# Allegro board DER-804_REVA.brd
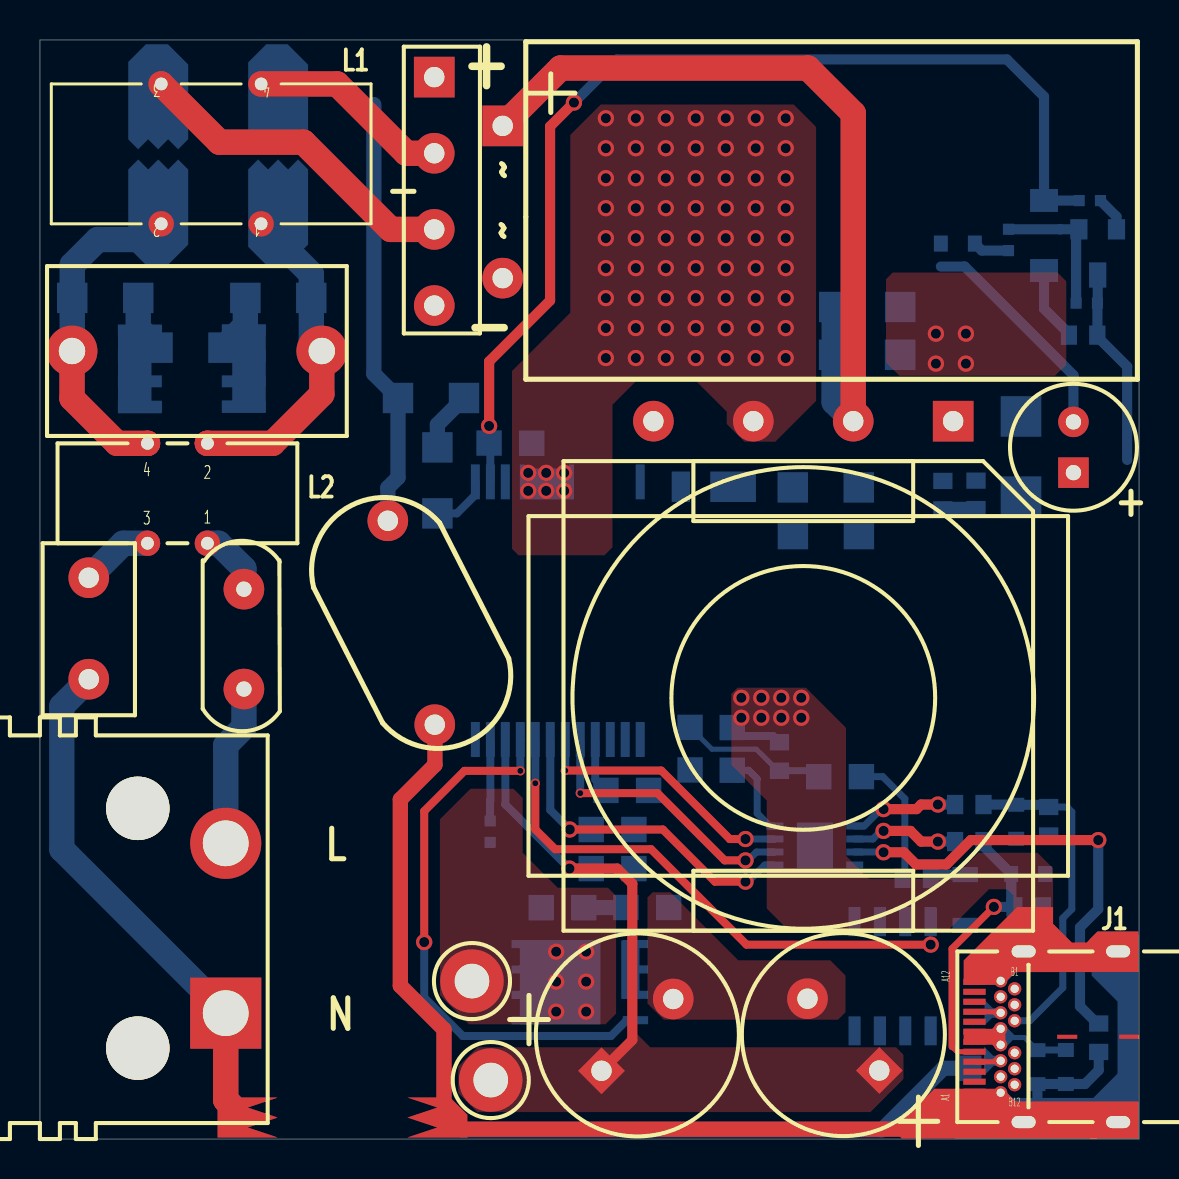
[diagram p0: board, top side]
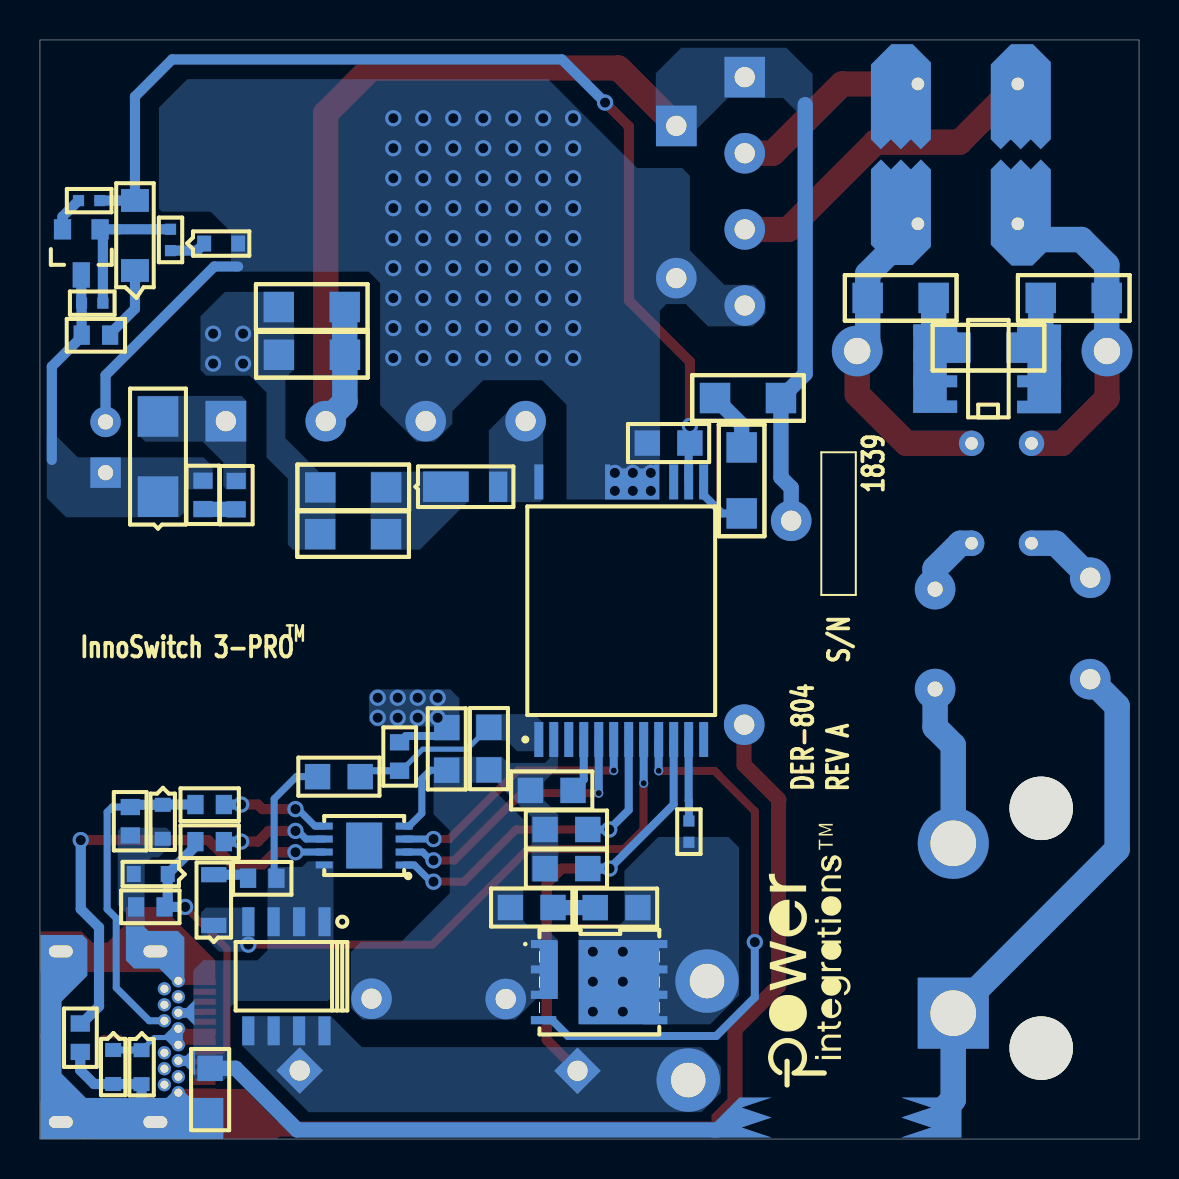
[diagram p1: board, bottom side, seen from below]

Outline 55 x 55 mm; copper layers: TOP, BOTTOM. Coordinates in mm from the lower left corner of the outline.
Outline path: 0,55 55,55 55,0 0,0 0,55

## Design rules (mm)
constraint set DEFAULT: min track width 0.508

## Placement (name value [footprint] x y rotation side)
BR1  UD4KB100-BP  [PIDAXBRIDGED3K]  19.73 53.14 270 top
C1  1 nF  [PINPYCAPRAD540X290LS400040]  17.41 30.94 297 top
C2  2.2 nF  [PISMC1206]  39.74 39.25 0 bottom
C3  100 uF  [PIPOLCAPCLYD630LS300040]  24.46 50.7 270 top
C4  470 uF  [PIPOLCAPCYLD400LS200040]  28.1 3.42 45 top
C5  470 uF  [PIPOLCAPCYLD400LS200040]  42 3.43 135 top
C6  1 uF  [PISMC0805]  46.48 3.54 270 bottom
C7  56 pF  [PISMC0603]  45.18 31.51 90 bottom
C8  1 nF  [PISMC0805]  29.33 11.59 0 bottom
C9  2.2 uF  [PISMC0805]  29.72 13.53 180 bottom
C10  330 nF  [PINP_XCAPRAD15X8P5X14HD040]  1.6 39.43 0 top
C11  4.7 uF  [PISMC0805]  32.53 18.47 90 bottom
C12  2.2 uF  [PISMC0805]  29.72 15.49 180 bottom
C13  2.2 uF  [PISMC0805]  30.46 17.45 180 bottom
C14  22 uF  [PIPOLCAPCYLD250LS100030]  51.72 33.35 90 top
C15  560 pF  [PISMC0603]  48.77 11.62 0 bottom
C16  560 pF  [PISMC0603]  50.48 16.61 270 bottom
C17  4.7 uF  [PISMC0805]  22.48 34.83 0 bottom
D1  DFLR1800-7  [PISMDDFLR120012]  34.71 32.64 0 bottom
D2  BAV21WS-7-F  [PISMSOD323]  46.3 10.69 90 bottom
D3  RS1J  [PISMDSMA]  49.09 32.15 90 bottom
D4  DZ2J240M0L  [PI_SM_D_SSMINI2P]  49.92 4.45 270 bottom
D5  DZ2J240M0L  [PI_SM_D_SSMINI2P]  51.34 4.45 270 bottom
D6  DZ2J240M0L  [PI_SM_D_SSMINI2P]  48.61 13.26 0 bottom
D7  DZ2J240M0L  [PI_SM_D_SSMINI2P]  48.86 16.73 270 bottom
F1  2 A  [PI_RST_MICROFUSE]  2.44 23.01 90 top
FL1  Hole_70mils  [PI_HOLE_70MIL]  22.56 2.93 0 top
FL2  Hole_70mils  [PI_HOLE_70MIL]  21.62 7.88 0 top
J1  CON24_USB_C  [PI_CONN_USBC_WURTH]  48.78 5.12 90 top
J2  CON2  [PI_IEC320-C8]  9.3 6.3 90 top
L1  ~16 mH  [PI_TOROID_CMC15X7_4P_V]  11.07 45.8 180 top
L2  250 uH  [PI_TOROID_CMC4P_H]  8.38 29.81 180 top
NOREF  -  []  0 0 0 top
NOREF#2  -  []  55 0 90 top
NOREF#3  -  []  19 2.59 90 bottom
Q1  AO4354  [PISMSO8]  40.76 10.88 0 bottom
Q2  AON6250  [PISMPQFN5X6B]  29.8 9.76 270 bottom
Q3  MMBTA06LT1G  [PISMSOT23123_1]  53.87 45.52 0 bottom
R1  232 k  [PISMR1206]  39.75 41.64 0 bottom
R2  40.2  [PISMR1206]  40.98 30.27 180 bottom
R3  100  [PISMR0603]  44.59 13.05 180 bottom
R4  2.00 M  [PISMR1206]  21.22 37.08 180 bottom
R5  40.2  [PISMR1206]  40.97 32.61 180 bottom
R6  487 k  [PISMR0805]  41.11 18.13 180 bottom
R7  5.6  [PISMR0805]  27.21 11.58 180 bottom
R8  1 M  [PISMR1206]  5.88 39.6 0 bottom
R9  1.80 M  [PISMR1206]  19.89 31.31 90 bottom
R10  22  [PISMR0603]  46.84 32.95 270 bottom
R11  0.006  [PISMR0805]  34.64 18.46 90 bottom
R12  10  [PISMR0603]  37 18.43 90 bottom
R13  1 M  [PISMR1206]  1.62 42.09 0 bottom
R14  1 M  [PISMR1206]  10.28 42.09 0 bottom
R15  47  [PISMR0402]  22.53 14.85 90 bottom
R16  130.0 k  [PISMR0402]  52.92 41.83 180 bottom
R17  22  [PISMR0603]  52.91 40.23 180 bottom
R18  7.15 k  [PISMR0402]  48.47 45.53 270 bottom
R19  7.15 k  [PISMR0402]  53.07 46.96 180 bottom
R20  22  [PISMR0603]  47.22 14.88 180 bottom
R21  22  [PISMR0603]  47.22 16.74 180 bottom
RT1  100 k  [PISMR0603]  52.98 4.36 90 bottom
RT2  2.5  [PI_RAD150X300LS200D030]  10.21 27.52 270 top
T1  EQ2506  [PI_BOBBIN_EQ-2506_4P]  45.7 35.92 270 top
U1  CAP200DG  [PI_IC_SMD_SO8_CAPZERO]  5 36.65 90 bottom
U2  INN3368C  [PI_IC_INSOP_24D]  30.04 19.99 90 bottom
U3  VP302  [PI_SM_DFN-8]  36.77 13.71 90 bottom
VR1  MMSZ5259BT1G  [PI_SM_SOD-123_12]  50.25 43.46 90 bottom
VR2  DZ2S08200L  [PI_SM_D_SSMINI2P]  46.78 44.81 180 bottom

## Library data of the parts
BR1 = DISCRETE BRIDGE_+~~-: alternate symbols: (pidaxbridgeD3K_horz)
C1 = CAP NP: alternate symbols: (pinpycaprad540x290ls400040h,pinpycaprad500x220ls400040)
C2 C6 C7 C9 C11-C13 C15-C17 = CAP NP
C3 = CAP POL: alternate symbols: (pipolcapclyd630ls3000401120h)
C4 C5 = CAP POL
C8 = CAP NP: alternate symbols: (pismc0805_1)
C10 = CAP NP: alternate symbols: (pinp_xcaprad15x8p5x14Hd040H)
C14 = CAP POL: alternate symbols: (pipolcapcyld250ls100030h)
D1-D3 = DIODE
D4-D7 VR1 VR2 = DIODE_ZENER
F1 = FUSE: alternate symbols: (pirstmicrofusehoz)
FL1 FL2 = FlyingLead
J1 = CON24_USB
J2 = CON2_ACIN
L1 = TORRID 4P_14_23
L2 = TORRID 4P_12_34: alternate symbols: (pi_toroid_CMC4p_V,pi_toroid_CMC4p_V_275uH)
Q1 Q2 = FET_N_SGD_123_4_5678
Q3 = NPN_BEC
R1-R21 = R
RT1 = THERMISTOR
RT2 = THERMISTOR: alternate symbols: (pirad400x300ls200040_h)
T1 = BEQ2506_4P
U1 = CAPZero
U2 = DEV_InnoPro
U3 = VP302

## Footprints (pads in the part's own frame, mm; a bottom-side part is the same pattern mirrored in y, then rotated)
PI_BOBBIN_EQ-2506_4P
  rect 2.032x2.032 hole 1.016: 1(0,0)
  round 2.032 hole 1.016: 2(0,-5) 3(0,-10) 4(0,-15)
PI_CONN_USBC_WURTH
  oval 1x1.6 hole 0.6x1.2: (-4.27,-0.45) (-4.27,-5.18) (4.27,-0.45) (4.27,-5.18)
  round 0.66 hole 0.406: (-2,0.7) (2,0.7) B1(2.8,0.7) B2(2.4,0) B3(1.6,0) B4(1.2,0.7) B5(0.8,0) B6(0.4,0.7) B7(-0.4,0.7) B8(-0.8,0) B9(-1.2,0.7) B10(-1.6,0) B11(-2.4,0) B12(-2.8,0.7)
  rect 0.305x1.118 smd: A1(-2.75,2.01) A2(-2.25,2.01) A3(-1.75,2.01) A4(-1.25,2.01) A5(-0.75,2.01) A6(-0.25,2.01) A7(0.25,2.01) A8(0.75,2.01) A9(1.25,2.01) A10(1.75,2.01) A11(2.25,2.01) A12(2.75,2.01)
PI_HOLE_70MIL
  round 3.175 hole 1.727: 1(0,0.025)
PI_IC_INSOP_24D
  rect 1.75x0.45 smd: 1(0,0) 2(0,-0.75) 3(0,-1.5) 4(0,-2.25) 5(0,-3) 6(0,-3.75) 7(0,-4.5) 8(0,-5.25) 9(0,-6) 10(0,-6.75) 11(0,-7.5) 12(0,-8.25) 13(12.89,-8.25) 14(12.89,-7.5) 15(12.89,-6.75) 24(12.89,0)
  custom 0.438x0.438 smd: 16(12.89,-4.67)
PI_IC_SMD_SO8_CAPZERO
  rect 0.599x2.2 smd: 1(0,0) 2(1.27,0) 3(2.54,0) 4(3.81,0) 5(3.81,5.199) 6(2.54,5.199) 7(1.27,5.199) 8(0,5.199)
PI_IEC320-C8
  round 3.175 hole 3.175 unplated: (-1.75,4.4) (10.25,4.4)
  rect 3.556x3.556 hole 2.286: 1(0,0)
  round 3.556 hole 2.286: 2(8.5,0)
PI_RAD150X300LS200D030
  round 2.032 hole 0.762: 1(0,0) 2(5,0)
PI_RST_MICROFUSE
  round 2.032 hole 1.016: 1(0,0) 2(5.08,0)
PI_SM_D_SSMINI2P
  rect 0.699x0.8 smd: 1(0,0) 2(1.7,0)
PI_SM_DFN-8
  rect 0.35x0.85 smd: 1(0,0) 2(0.65,0) 3(1.3,0) 4(1.95,0) 5(1.95,4) 6(1.3,4) 7(0.65,4) 8(0,4)
  rect 2.3x1.8 smd: 9(0.975,2)
PI_SM_SOD-123_12
  rect 1.143x1.397 smd: 1(0,0) 2(3.505,0)
PI_TOROID_CMC4P_H
  round 1.27 hole 0.635: 1(0,0) 2(0,-5) 3(3,0) 4(3,-5)
PI_TOROID_CMC15X7_4P_V
  round 1.27 hole 0.635: 1(0,0) 2(5,0) 3(5,-7) 4(0,-7)
PIDAXBRIDGED3K
  rect 2.032x2.032 hole 1.016: 1(0,0)
  round 2.032 hole 1.016: 2(3.81,0) 3(7.62,0) 4(11.43,0)
PINP_XCAPRAD15X8P5X14HD040
  round 2.54 hole 1.321: 1(0,0) 2(12.5,0)
PINPYCAPRAD540X290LS400040
  round 2.032 hole 1.016: 1(0,0) 2(10.16,-2.54)
PIPOLCAPCLYD630LS300040
  rect 2.032x2.032 hole 1.016: 1(0,-1.3)
  round 2.032 hole 1.016: 2(7.62,-1.3)
PIPOLCAPCYLD250LS100030
  rect 1.524x1.524 hole 0.762: 1(0,0)
  round 1.524 hole 0.762: 2(2.54,0)
PIPOLCAPCYLD400LS200040
  rect 1.651x1.651 hole 1.016: 1(0,0)
  round 2.032 hole 1.016: 2(5.08,0)
PISMC0603
  rect 0.813x0.965 smd: 1(0,0) 2(1.422,0)
PISMC0805
  rect 1.27x1.27 smd: 1(0,0) 2(2.134,0)
PISMC1206
  rect 1.524x1.524 smd: 1(0,0) 2(3.302,0)
PISMDDFLR120012
  rect 2.286x1.524 smd: 1(-0.025,0)
  rect 0.914x1.524 smd: 2(-2.642,0)
PISMDSMA
  rect 2.032x2.032 smd: 1(0,0) 2(4.013,0)
PISMPQFN5X6B
  rect 0.406x1.27 smd: 1(0,0) 2(1.27,0) 3(2.54,0) 4(3.81,0)
  rect 0.406x1.219 smd: 5(3.81,5.588) 6(2.54,5.588) 7(1.27,5.588) 8(0,5.588)
PISMR0402
  rect 0.559x0.559 smd: 1(0,0) 2(1.067,0)
PISMR0603
  rect 0.813x0.965 smd: 1(0,0) 2(1.422,0)
PISMR0805
  rect 1.27x1.27 smd: 1(0,0) 2(2.134,0)
PISMR1206
  rect 1.524x1.524 smd: 1(0,0) 2(3.302,0)
PISMSO8
  rect 0.61x1.448 smd: 1(0,0) 2(1.27,0) 3(2.54,0) 4(3.81,0) 5(3.81,5.461) 6(2.54,5.461) 7(1.27,5.461) 8(0,5.461)
PISMSOD323
  rect 0.762x1.27 smd: 1(0,0) 2(2.54,0)
PISMSOT23123_1
  rect 0.864x1.016 smd: 1(-1.88,0) 2(0,0)
  rect 0.864x1.27 smd: 3(-0.94,2.286)

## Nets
VBUS: C6.1 J1.A4 J1.A9 J1.B4 J1.B9(VBUS4) Q1.1 Q1.2 Q1.3(S3) R3.2 R6.1 U3.8
NC3: U2.3
RTN: C1.2 C6.2 C15.2 C16.2 D4.2 D5.2 D6.2 D7.2 J1.A1 J1.A12 J1.B1 J1.B12 R11.2 R12.2 RT1.1
S: C4.2 C5.2 C8.2 C9.1 C11.1 C12.1 C13.1 Q2.1 Q2.2 Q2.3(S3) R11.1 U2.2 U3.4
N11110714: BR1.1 C1.1 C2.1 C3.1 R1.1 R4.2 T1.2
N11110720: BR1.4 C3.2 C14.2 C17.2 T1.3 U2.16 VR2.2
N11111408: R4.1 R9.2
N11111567: C2.2 R1.2 R2.1 R5.1
N11111589: D1.1 R2.2 R5.2
N11116283: D1.2 T1.4 U2.24
N11116458: R9.1 U2.13
N12069038: R17.2 VR1.1
N12069042: Q3.1 R16.2 R18.1
N12069064: C14.1 D3.1 Q3.3 R10.1 R16.1 R17.1
N12069074: Q3.2(EMITTER) R19.1
N12069082: C17.1 R19.2 U2.14 VR1.2
N12069495: C7.2 D3.2 T1.1
N12158517: C7.1 R10.2
N12177631: C4.1 C5.1 C9.2 FL1.1 Q1.5 Q1.6 Q1.7 Q1.8 U2.10(VOUT)
N12177765: D2.1 Q1.4 U2.8
N12177789: D2.2 R3.1
N12177915: C11.2 R6.2 R12.1 U2.1
N12177961: FL2.1 Q2.5 Q2.6 Q2.7 Q2.8 R7.2 R15.1
N12178241: D4.1 D5.1 J1.A6 J1.A7 J1.B6 J1.B7
N12178281: C15.1 D6.1 J1.A5 R20.1
N12178289: C16.1 D7.1 J1.B5 R21.1
N12178365: R15.2 U2.11
N12178457: RT1.2 U3.7
N12178487: C13.2 U2.4
N12178515: C12.2 U2.7 U3.1(VCC)
N12178621: U2.6 U3.3
N12178625: U2.5 U3.2
N12178783: R20.2 U3.6
N12178819: R21.2 U3.5
N12182535: C8.1 R7.1
N12188880: Q2.4 U2.9
N12193829: R18.2 VR2.1
N12198989: C10.1 L1.2 L2.4 R13.1
N12198993: C10.2 L1.1 L2.2 R14.2
N12199029: R8.1 R13.2 U1.2
N12199033: R8.2 R14.1 U1.7
N12199195: F1.2 L2.3
N12199199: L2.1 RT2.1
N12199291: F1.1 J2.1
N12199295: J2.2 RT2.2
N12200850: BR1.3(AC2) L1.3
N12200878: BR1.2 L1.4

Pads without a net: J1 A2 A3 A8 A10 A11 B2 B3 B8 B10 B11; U1 1 3 4 5 6 8; U2 12 15; U3 9

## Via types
v1: diameter 0.813, hole 0.508, TOP to BOTTOM, 103 vias
v2: diameter 0.457, hole 0.305, TOP to BOTTOM, 4 vias

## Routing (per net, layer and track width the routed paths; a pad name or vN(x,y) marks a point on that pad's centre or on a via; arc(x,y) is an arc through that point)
VBUS: length 36
  TOP w0.254: J1.B4 47.8,6.32 47.75,6.37 J1.A9 ; J1.A4 47.75,3.87 47.8,3.92 J1.B9
  BOTTOM w0.35: R3.2 43.28,13.17 43.28,17.02 42.17,18.13 R6.1
  BOTTOM w0.762: 21.11,0.46 42.13,0.46 45.21,3.54 C6.1
RTN: length 56.3
  TOP w0.254: J1.B1 47.8,7.92 47.75,7.87 J1.A12 ; J1.B12 47.8,2.32 47.75,2.37 J1.A1
  TOP w0.762: 46.24,0.5 20.92,0.5 ; 20.22,1.91 20.22,5.49 18.03,7.67 18.03,16.99 19.76,18.72 19.76,20.73 C1.2
  TOP w1.27: 49.35,10.97 49.38,10.95
  BOTTOM w0.4: R11.2 35.06,20.17 36.69,20.17 R12.2
  BOTTOM w0.508: 49.91,1.83 49.92,1.83 D4.2 49.92,2.75 D5.2 52.29,2.75 52.98,3.44 RT1.1
  vias: v1(35.1,22.08) v1(35.1,21.08) v1(36.1,22.08) v1(36.1,21.08) v1(37.1,22.08) v1(37.1,21.08) v1(38.1,22.08) v1(38.1,21.08)
S: length 4.3
  BOTTOM w0.35: R11.1 35.46,18.46 35.89,18.03 35.89,16.3 36.52,15.66 U3.4
N11110714: length 62.7
  TOP w1.27: T1.2 40.7,51.33 38.43,53.59 26.05,53.59 C3.1
  BOTTOM w0.762: C1.1 17.41,32.59 17.92,33.1 R4.2 16.71,38.29 16.71,51.77
  BOTTOM w1.27: T1.2 39.74,36.88 C2.1 39.75,39.25 R1.1
N11110720: length 11.2
  BOTTOM w0.508: C14.2 51.72,38.22 46.28,43.66 45.09,43.66
  vias: v1(24.43,33.34) v1(24.43,32.44) v1(25.33,33.34) v1(25.33,32.44) v1(26.23,33.34) v1(26.23,32.44) v1(28.32,51.08) v1(28.32,49.58) v1(28.32,48.08) v1(28.32,46.58) v1(28.32,45.08) v1(28.32,43.58) v1(28.32,42.08) v1(28.32,40.58) v1(28.32,39.08) v1(29.82,51.08) v1(29.82,49.58) v1(29.82,48.08) v1(29.82,46.58) v1(29.82,45.08) v1(29.82,43.58) v1(29.82,42.08) v1(29.82,40.58) v1(29.82,39.08) v1(31.32,51.08) v1(31.32,49.58) v1(31.32,48.08) v1(31.32,46.58) v1(31.32,45.08) v1(31.32,43.58) v1(31.32,42.08) v1(31.32,40.58) v1(31.32,39.08) v1(32.82,51.08) v1(32.82,49.58) v1(32.82,48.08) v1(32.82,46.58) v1(32.82,45.08) v1(32.82,43.58) v1(32.82,42.08) v1(32.82,40.58) v1(32.82,39.08) v1(34.32,51.08) v1(34.32,49.58) v1(34.32,48.08) v1(34.32,46.58) v1(34.32,45.08) v1(34.32,43.58) v1(34.32,42.08) v1(34.32,40.58) v1(34.32,39.08) v1(35.82,51.08) v1(35.82,49.58) v1(35.82,48.08) v1(35.82,46.58) v1(35.82,45.08) v1(35.82,43.58) v1(35.82,42.08) v1(35.82,40.58) v1(35.82,39.08) v1(37.32,51.08) v1(37.32,49.58) v1(37.32,48.08) v1(37.32,46.58) v1(37.32,45.08) v1(37.32,43.58) v1(37.32,42.08) v1(37.32,40.58) v1(37.32,39.08)
N11111408: length 3
  BOTTOM w0.762: R4.1 19.89,35.75 R9.2
N11111567:
  vias: v1(44.84,40.3) v1(44.84,38.8) v1(46.34,40.3) v1(46.34,38.8)
N11116458: length 2.9
  BOTTOM w0.4: U2.13 21.79,32.23 20.86,31.31 R9.1
N12069038: length 3.7
  BOTTOM w0.508: R17.2 51.49,40.31 50.25,41.55 VR1.1
N12069042: length 7.3
  BOTTOM w0.508: R18.1 51.05,45.53 51.05,45.52 Q3.1 51.85,45.38 R16.2
N12069064: length 9.9
  BOTTOM w0.508: 54.41,33.99 54.41,38.66 52.91,40.15 R17.1 52.92,40.24 R16.1 52.93,41.84 Q3.3
N12069074: length 1.8
  BOTTOM w0.508: Q3.2 53.87,46.16 R19.1
N12069082: length 52.9
  TOP w0.508: v1(26.72,51.87) 25.53,50.67 25.53,41.96 22.48,38.91 v1(22.48,35.68)
  BOTTOM w0.4: U2.14 22.54,34.77 C17.1
  BOTTOM w0.508: C17.1 v1(22.48,35.68) ; v1(26.72,51.87) 28.88,54.03 48.39,54.03 50.25,52.17 VR1.2 50.25,46.96 R19.2
N12158517: length 1.7
  BOTTOM w0.762: C7.1 46.83,31.51 R10.2
N12177631: length 22.3
  TOP w0.508: C4.1 29.64,4.96 29.64,12.78 28.88,13.53 v1(26.5,13.53)
  BOTTOM w0.4: U2.10 23.29,16.74 v1(26.5,13.53)
  BOTTOM w0.508: C9.2 v1(26.5,13.53)
N12177765: length 26.7
  TOP w0.4: v1(44.57,9.73) 35.36,9.73 30.58,14.5 25.78,14.5 24.79,15.5 v2(24.79,17.81)
  BOTTOM w0.4: U2.8 v2(24.79,17.81)
N12177789: length 1.8
  BOTTOM w0.508: R3.1 44.59,13.13 44.69,13.23 D2.2
N12177915: length 7.5
  BOTTOM w0.254: R12.1 36.93,18.43 35.85,19.51 33.63,19.51 C11.2
  BOTTOM w0.35: R12.1 38.68,18.43 R6.2
N12177961:
  vias: v1(25.83,9.38) v1(25.83,7.88) v1(25.83,6.38) v1(27.33,9.38) v1(27.33,7.88) v1(27.33,6.38)
N12178241: length 2.9
  BOTTOM w0.254: D4.1 49.91,4.45 49.28,5.08 48.72,5.08
  BOTTOM w0.35: D5.1 49.92,4.45 D4.1
N12178281: length 14
  TOP w0.254: J1.A5 45.9,4.37 45.64,4.62
  TOP w0.35: 45.64,4.62 45.64,9.53 v1(47.73,11.62)
  BOTTOM w0.508: v1(47.73,11.62) C15.1 48.61,11.78 D6.1 47.22,14.65 R20.1
N12178289: length 16.7
  BOTTOM w0.35: J1.B5 49.53,5.92 51.18,7.57 51.18,11.05 51.64,11.51 51.64,16.36 51.39,16.61 C16.1
  BOTTOM w0.508: R21.1 48.84,16.74 D7.1 50.37,16.73 C16.1
N12178365: length 4.1
  BOTTOM w0.4: U2.11 22.54,16.94 22.53,16.93 R15.2
N12178457: length 22.9
  TOP w0.508: v1(42.21,14.35) 43.23,14.35 43.84,13.74 45.36,13.74 46.58,14.96 v1(52.96,14.96)
  BOTTOM w0.35: U3.7 42.2,14.36 v1(42.21,14.35)
  BOTTOM w0.508: RT1.2 52.91,5.78 52.04,6.64 52.04,10.59 52.96,11.51 v1(52.96,14.96)
N12178487: length 2.8
  BOTTOM w0.4: C13.2 27.79,17.98 U2.4
N12178515: length 17.7
  TOP w0.4: v1(35.31,12.88) 33.78,12.88 31.17,15.49 v1(26.51,15.49)
  BOTTOM w0.35: U3.1 36.27,13.71 35.43,12.88 v1(35.31,12.88)
  BOTTOM w0.4: U2.7 25.54,16.46 v1(26.51,15.49) C12.2
N12178621: length 13.5
  TOP w0.4: v2(26.29,18.44) 31.09,18.44 34.52,15.01 v1(35.31,15.01)
  BOTTOM w0.35: U3.3 35.31,15.01 v1(35.31,15.01)
  BOTTOM w0.4: U2.6 v2(26.29,18.44)
N12178625: length 14
  TOP w0.4: v2(27.04,17.31) 30.9,17.31 34.26,13.94 v1(35.31,13.94)
  BOTTOM w0.35: v1(35.31,13.94) 35.43,13.94 35.85,14.36 U3.2
  BOTTOM w0.4: U2.5 v2(27.04,17.31)
N12178783: length 5.4
  TOP w0.508: v1(44.93,14.88) 44.09,14.88 43.56,15.42 v1(42.21,15.42)
  BOTTOM w0.35: v1(42.21,15.42) 42.09,15.42 41.68,15.01 U3.6
  BOTTOM w0.508: R20.2 v1(44.93,14.88)
N12178819: length 5.5
  TOP w0.508: v1(44.93,16.74) 44.09,16.74 43.87,16.51 v1(42.21,16.51)
  BOTTOM w0.35: U3.5 41.24,15.66 42.09,16.51 v1(42.21,16.51)
  BOTTOM w0.508: R21.2 v1(44.93,16.74)
N12182535: length 2.1
  BOTTOM w0.762: R7.1 29.09,11.58 29.1,11.59 C8.1
N12188880: length 28.2
  TOP w0.4: v1(19.23,9.86) 19.23,16.41 21.24,18.42 v2(24.04,18.42)
  BOTTOM w0.4: v1(19.23,9.86) 19.23,7.09 21.16,5.16 28.58,5.16 29.37,5.95 Q2.4 ; U2.9 v2(24.04,18.42)
N12193829: length 1.8
  BOTTOM w0.508: R18.2 47.13,44.46 VR2.1
N12198989: length 16.2
  TOP w1.27: L2.4 3.86,34.81 1.6,37.07 C10.1
  BOTTOM w1.27: 5.85,45.01 2.89,45.01 1.62,43.74 R13.1 1.62,39.45 C10.1
N12198993: length 16.5
  TOP w1.27: C10.2 14.1,37.28 11.64,34.81 L2.2
  BOTTOM w1.27: L1.1 13.58,43.29 R14.2 13.58,39.96 C10.2
N12199029: length 4.9
  BOTTOM w0.254: R8.1 5,38.72 U1.2
  BOTTOM w1.27: R8.1 4.92,40.57 R13.2
N12199033: length 5
  BOTTOM w0.254: R8.2 10.2,38.59 U1.7
  BOTTOM w1.27: R14.1 10.28,40.69 R8.2
N12199195: length 3.7
  BOTTOM w1.27: F1.2 4.17,29.81 L2.3
N12199199: length 3.4
  BOTTOM w1.27: RT2.1 10.21,28.54 8.94,29.81 L2.1
N12199291: length 30.1
  TOP w1.27: 9.58,1.68 9.3,1.96 J2.1
  BOTTOM w1.27: 9.58,1.7 9.3,1.98 J2.1 1.1,14.5 1.1,21.66 F1.1
N12199295: length 8.1
  BOTTOM w1.27: J2.2 9.3,19.7 10.21,20.61 RT2.2
N12200850: length 16.7
  TOP w1.27: BR1.3 17.55,45.52 13.18,49.89 8.98,49.89 L1.3
N12200878: length 10.1
  TOP w1.27: BR1.2 18.34,49.33 14.87,52.8 L1.4

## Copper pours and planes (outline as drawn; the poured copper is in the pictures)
VBUS on BOTTOM (solid shape): 21.39,0.68 21.39,0.08 18.39,0.08 19.89,0.58 18.39,1.08 19.89,1.58 18.39,2.08 19.99,2.08
VBUS on BOTTOM (solid shape): 47.7,4.17 48.16,4.17 48.31,4.01 48.31,3.81 48.16,3.66 47.73,3.66 47.24,3.17 47.24,4.62
VBUS on BOTTOM (solid shape): 47.68,6.55 48.18,6.55 48.31,6.43 48.31,6.22 48.16,6.07 47.65,6.07 47.27,5.69 47.27,6.96
VBUS on BOTTOM: 40.31,7.19 40.59,6.91 45.16,6.91 45.52,6.55 45.52,3.23 45.85,2.9 47.14,2.9 47.32,3.07 47.32,8.43 46.81,8.94 44.12,8.94 43.61,9.45 43.61,13.51 43.51,13.61 41.88,13.61 41.61,13.89 40.31,13.89
Net_54 on BOTTOM (solid shape): 11.3,36.34 9.11,36.34 9.11,36.95 9.62,36.95 9.62,40.15 9.11,40.15 9.11,40.76 11.3,40.76
Net_58 on BOTTOM (solid shape): 6.09,40.13 5.58,40.13 5.58,36.93 6.09,36.93 6.09,36.32 3.91,36.32 3.91,40.74 6.09,40.74
RTN on TOP (solid shape): 54.97,0.03 52.55,0.03 52.55,1.52 52.91,1.88 54.97,1.88
RTN on TOP (solid shape): 54.97,8.36 52.86,8.36 52.53,8.69 52.53,9.98 52.93,10.39 54.97,10.39
RTN on TOP (solid shape): 21.39,1.22 21.39,0.08 18.39,0.08 19.89,0.58 18.39,1.08 19.89,1.58 18.39,2.08 20.53,2.08
RTN on TOP (solid shape): 48.82,1.88 52.91,1.88 52.91,0.03 43.13,0.03 42.95,0.2 42.95,0.71 44.75,2.51 48.18,2.51
RTN on TOP (solid shape): 50.7,10.77 51.64,9.83 52.37,9.83 52.93,10.39 52.93,8.43 52.86,8.36 48.82,8.36 48.18,7.72 46.23,7.72 46.23,8.94 48.9,11.61 50.7,11.61
RTN on BOTTOM (solid shape): 48.67,2.06 52.7,2.06 52.7,0.03 45.82,0.03 45.82,2.06 47.47,2.06 47.96,2.54 48.18,2.54
RTN on BOTTOM (solid shape): 50.7,8.94 50.29,8.53 49.02,8.53 48.18,7.7 47.93,7.7 47.78,7.85 47.78,10.08 48.11,10.41 49.58,10.41 49.81,10.64 50.7,10.64
RTN on BOTTOM (solid shape): 54.97,0.03 52.63,0.03 52.63,1.98 53.92,3.28 53.92,6.88 52.63,8.18 52.63,9.96 52.88,10.21 54.97,10.21
RTN on TOP: 36.37,11.53 37.47,10.44 45.44,10.44 47.5,12.5 48.41,12.5 48.72,12.19 48.72,11.3 50.7,11.3 50.7,13.54 49.91,14.33 46.96,14.33 45.67,13.03 41.48,13.03 40.34,14.17 40.34,20.57 38.33,22.58 34.9,22.58 34.59,22.28 34.59,18.72 36.37,16.94
RTN on BOTTOM: 35.23,20.02 35.18,19.96 34.01,19.96 34.01,22.05 34.47,22.5 38.28,22.5 38.53,22.25 38.53,20.93 38.25,20.65 35.28,20.65 35.23,20.6
RTN on BOTTOM: 48.46,15.37 48.46,14.68 49.05,14.1 49.4,14.1 49.76,13.74 49.76,10.57 50.7,10.57 50.7,11.3 51.1,11.71 51.1,15.42 50.94,15.58 48.68,15.58
S on BOTTOM (solid shape): 30,7.01 29.09,7.01 29.09,9.94 30,9.94
S on TOP: 31.22,5.97 30.4,6.78 30.4,12.09 30.66,12.34 31.55,12.34 34.95,8.94 39.55,8.94 40.31,8.18 40.31,6.35 39.93,5.97
S on BOTTOM: 29.08,20.85 29.49,20.85 29.49,19.05 29.72,18.82 31.57,18.82 31.88,19.13 35.26,19.13 35.31,19.08 35.31,16.26 34.49,15.44 34.49,12.29 36.91,9.88 38.91,9.88 39.45,9.35 39.45,6.55 38.86,5.97 31.22,5.97 30.18,7.01 29.08,7.01 29.08,9.96 29.64,10.52 30.4,10.52 30.81,10.92 30.81,16 32.26,17.45 33.38,17.45 33.48,17.55 33.48,17.73 33.38,17.83 32.13,17.83 30.4,16.1 30.4,12.93 30.35,12.88 29.08,12.88 29.06,12.9 29.06,16.23 29.77,16.94 29.77,17.88 29.08,18.57
N11110714 on BOTTOM: 24.18,49.68 24.18,53.34 22.91,54.61 17.65,54.61 16.33,53.29 16.33,51.56 16.54,51.36 17.07,51.36 17.81,52.1 20.57,52.1 22.12,50.55 22.12,49.68
N11110720 on TOP: 35.26,34.9 36.8,34.9 38.84,36.93 38.84,50.65 37.72,51.77 28.07,51.77 26.54,50.24 26.54,41.35 23.62,38.43 23.62,29.54 23.95,29.21 28.24,29.21 28.65,29.62 28.65,36.75 29.87,37.97 31.52,37.97 31.53,37.96 32.8,37.96 34.37,36.4 34.37,35.79
N11110720 on BOTTOM: 23.98,32 23.98,41.45 23.65,41.78 22.68,41.78 21.56,40.67 19.33,40.67 18.69,41.3 18.69,42.16 19.28,42.75 20.75,42.75 22.48,44.48 22.48,48.21 22.86,48.59 25.12,48.59 29.57,53.04 47.62,53.04 49.05,51.61 49.05,46.56 48.9,46.41 46.46,46.41 45.44,45.39 45.44,43.56 45.29,43.41 38.56,43.41 37.97,42.82 37.97,36.73 36.14,34.9 35.26,34.9 34.37,35.79 34.37,36.42 32.82,37.97 29.87,37.97 28.65,36.75 28.65,32
N11111567 on TOP: 42.34,43.03 42.34,38.86 43,38.2 50.8,38.2 51.36,38.76 51.36,42.93 50.93,43.36 42.67,43.36
N11111567 on BOTTOM: 42.6,29.74 42.6,33.05 43.66,34.11 43.66,37.36 44.5,38.2 46.69,38.2 46.96,38.48 46.96,41.17 45.75,42.39 42.29,42.39 42.29,38.51 42.72,38.07 42.72,35.08 41.02,33.38 40.21,33.38 40.21,29.49 42.34,29.49
N11111589 on BOTTOM: 33.55,33.4 38.46,33.4 38.46,29.49 35.99,29.49 33.55,31.93
N11116283 on BOTTOM: 29.82,32.03 29.82,36.22 30.2,36.6 31.39,36.6 32.54,35.46 32.54,31.88 29.97,31.88
N12069064 on BOTTOM: 46.35,32.51 47.6,32.51 47.8,32.31 47.8,31.34 48.03,31.11 53.7,31.11 54.66,32.08 54.66,35.23 54.23,35.23 53.11,34.11 46.81,34.11 46.35,33.66
N12069495 on BOTTOM: 44.68,36.96 44.91,37.19 50.04,37.19 50.09,37.13 50.09,35.26 49.73,34.9 46.86,34.9 45.82,33.86 45.82,32.66 45.67,32.51 44.68,32.51
N12177631 on TOP: 21.89,4.6 28.96,4.6 29.64,5.28 29.84,5.28 30.53,4.6 42.82,4.6 43.21,4.22 43.21,3 41.55,1.35 21.89,1.35 20.93,2.31 20.93,3.63
N12177631 on BOTTOM: 38.89,4.6 21.89,4.6 20.93,3.63 20.93,2.31 21.89,1.35 41.55,1.35 44.88,4.67 44.88,6.15 40.44,6.15
N12177765 on BOTTOM: 46.69,11.58 46.94,11.33 46.94,10.29 46.02,9.37 44.53,9.37 44.27,9.63 44.27,11.58
N12177915 on BOTTOM: 29.87,19.41 31.11,19.41 31.65,19.94 33.2,19.94 33.2,21.26 30.25,21.26 29.84,20.85 29.84,19.43
N12177961 on BOTTOM (solid shape): 28.05,5.74 24.01,5.74 24.01,9.96 28.05,9.96
N12177961 on TOP: 21.46,5.74 28.3,5.74 28.83,6.27 28.83,12.17 28.42,12.57 25.91,12.57 24.16,14.33 24.16,17.07 23.7,17.53 21.54,17.53 20.02,16 20.02,7.19
N12177961 on BOTTOM: 20.02,7.19 20.02,14.58 20.55,15.11 24.05,15.11 25.76,13.41 25.76,10.95 26.21,10.49 27.91,10.49 28.04,10.36 28.04,5.87 27.91,5.74 21.46,5.74
N12178241 on TOP (solid shape): 48.31,5.61 48.31,4.62 48.18,4.5 47.88,4.5 47.65,4.72 46.23,4.72 46.23,5.51 47.65,5.51 47.88,5.74 48.18,5.74
N12178241 on BOTTOM (solid shape): 48.82,5.16 48.82,5.08 48.23,4.5 47.98,4.5 47.85,4.62 47.85,5.61 47.98,5.74 48.23,5.74
N12198989 on BOTTOM (solid shape): 7.42,48.52 7.42,44.75 6.38,43.71 5.33,43.71 4.42,44.63 4.42,48.52 4.92,49.02 5.42,48.52 5.92,49.02 6.42,48.52 6.92,49.02
N12198993 on BOTTOM (solid shape): 13.42,48.52 13.42,44.76 12.4,43.74 11.33,43.74 10.42,44.65 10.42,48.52 10.92,49.02 11.42,48.52 11.92,49.02 12.42,48.52 12.92,49.02
N12199291 on TOP (solid shape): 10.39,1.58 11.89,1.08 10.39,0.58 11.89,0.08 8.89,0.08 8.89,2.08 11.89,2.08
N12199291 on BOTTOM (solid shape): 10.39,1.58 11.89,1.08 10.39,0.58 11.89,0.08 8.89,0.08 8.89,2.08 11.89,2.08
N12200850 on BOTTOM (solid shape): 7.42,53.77 7.42,50.03 6.92,49.53 6.42,50.03 5.92,49.53 5.42,50.03 4.92,49.53 4.42,50.03 4.42,53.9 5.31,54.79 6.4,54.79
N12200878 on BOTTOM (solid shape): 13.42,53.77 13.42,50.03 12.92,49.53 12.42,50.03 11.92,49.53 11.42,50.03 10.92,49.53 10.42,50.03 10.42,53.88 11.33,54.79 12.4,54.79

Small or netless copper shapes (teardrops, artwork), in the pictures only: 2 on TOP

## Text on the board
Ref Des/Silkscreen Bottom: TM | InnoSwitch 3-PRO | 1839 | S/N | REV A | DER-804
User.5: NPTH SLOTS | PTH SLOTS | 1.  THROUGH HOLES ARE PLATED THROUGH. | EXCEPTIONS WILL BE NOTED IN DRILL CHART "NOTE". | 2.  MATERIAL: BASE MATERIAL LAMINATED EPOXY | UL APPROVED MANUFACTURED SOURCE FOR FR4. | 3.  SOLDER PLATE WILL BE RoHS COMPLIANT. | 4.  SOLDER MASK LPI (LIQUID PHOTO IMAGEABLE) BOTH SIDES. COLOR GREEN. | SOLDER MASK (REGISTRATION) -0/+0.003" | 5.  SILKSCREEN TOP/BOTTOM SIDE. COLOR WHITE. (MIN.WIDTH 0.005" MAX.WIDTH 0.010") | 6.  FINISH TO BE SMOBC. | 7.  ELECTROLESS NICKEL IMMERSION GOLD (ENIG). | 8.  BOARD DIMENSION +/- 0.005" | 9.  DRILL TOLERANCE +/- 0.003" | 10. TRACE WIDTH UNDER 0.010" +/- 0.002" | TRACE WIDTH OVER 0.011" +/- 0.005" | 11. TRACE SPACE +/- 0.003" | 12. MATERIAL FR4 COPPER 2 OZ BOARD THICKNESS 0.062" | NOTES: UNLESS OTHERWISE SPECIFIED
User.8: FIGURE | FINISHED_SIZE | 12.0 | 16.0 | 20.0 | 25.0 | 30.0 | 40.0 | 52.0 | 68.0 | 90.0 | 125.0 | 47.244x23.622 | DRILL CHART: TOP to BOTTOM | ALL UNITS ARE IN MILS | PLATED | NON-PLATED | QTY | 4 | 14 | 103 | 8 | 2 | 16
